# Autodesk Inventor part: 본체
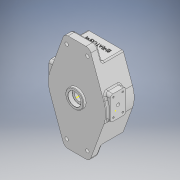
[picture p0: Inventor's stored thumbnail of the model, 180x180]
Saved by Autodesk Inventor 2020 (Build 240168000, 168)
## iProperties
Created: 2023-11
Part Number: 본체
Material: 일반
Document SubType Name: Modeling
Designer: CAD16
Density: 1 g/cm^3
Appearance: 기본값
Author: CAD16
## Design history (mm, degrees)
sketch "스케치1"
  geometry: L1 (-17.315, 94)-(17.315, 94); L2 (0, 94)-(0, 0); L3 (51.683, 18.811)-(26.711, 87.42); L4 (-51.683, 18.811)-(-26.711, 87.42); L5 (-55, 0)-(55, 0); L6 (51.683, -18.811)-(26.711, -87.42); L7 (-51.683, -18.811)-(-26.711, -87.42); L8 (-17.315, -94)-(17.315, -94); A1 r 55 centre (0, 0) between (-51.683, 18.811) and (51.683, 18.811); A2 r 10 centre (17.315, 84) between (26.711, 87.42) and (17.315, 94); A3 r 10 centre (-17.315, 84) between (-17.315, 94) and (-26.711, 87.42); A4 r 10 centre (-17.315, -84) between (-26.711, -87.42) and (-17.315, -94); A5 r 10 centre (17.315, -84) between (17.315, -94) and (26.711, -87.42); 7 further points
  constraints: 16 end point, 12 point on circle, 9 tangent, 8 point on line, 6 symmetric about line, 5 centre point, 2 equal radius, 2 horizontal, 2 midpoint, 1 coincident, 1 vertical
  dimensions: "d0" = 94 distance from line of point (0, 0) L1; "d1" = 110 diameter of A1; "d4" = 40 deg angle of L3 L4; "d119" = 10 radius of A2; "d120" = 10 radius of A3
extrude "돌출1" new body sketch "스케치1" distance "d5" = 15; taper "d6" = 0 deg
sketch "스케치2"
  geometry: L1 (-26.711, -87.42)-(-51.683, -18.811) reference; L2 (17.315, -94)-(-17.315, -94) reference; L3 (51.683, -18.811)-(26.711, -87.42) reference; L4 (26.711, 87.42)-(51.683, 18.811) reference; L5 (-17.315, 94)-(17.315, 94) reference; L6 (-51.683, 18.811)-(-26.711, 87.42) reference; L7 (-51.683, 18.811)-(-24.317, 94) reference; L8 (-33.78, 68)-(33.78, 68); L9 (24.317, 94)-(51.683, 18.811) reference; L10 (-24.317, -94)-(-51.683, -18.811) reference; L11 (-33.78, -68)-(33.78, -68); L12 (51.683, -18.811)-(24.317, -94) reference; L13 (24.317, 94)-(51.683, 18.811) reference; L14 (51.683, -18.811)-(24.317, -94) reference; L15 (-24.317, -94)-(-51.683, -18.811) reference; L16 (-51.683, 18.811)-(-24.317, 94) reference; L17 (-33.78, 68)-(-51.683, 18.811); L18 (-51.683, -18.811)-(-33.78, -68); L19 (33.78, -68)-(51.683, -18.811); L20 (51.683, 18.811)-(33.78, 68); C1 r 55 at (0, 0); A1 r 55 centre (0, 0) between (-51.683, 18.811) and (-51.683, -18.811) reference; A2 r 55 centre (0, 0) between (51.683, -18.811) and (51.683, 18.811) reference; A3 r 55 centre (0, 0) between (51.683, -18.811) and (51.683, 18.811) reference; A4 r 55 centre (0, 0) between (-51.683, 18.811) and (-51.683, -18.811) reference; A5 r 55 centre (0, 0) between (51.683, -18.811) and (51.683, 18.811) reference; A6 r 10 centre (17.315, 84) between (26.711, 87.42) and (17.315, 94) reference; A7 r 10 centre (-17.315, 84) between (-17.315, 94) and (-26.711, 87.42) reference; A8 r 10 centre (-17.315, -84) between (-26.711, -87.42) and (-17.315, -94) reference; A9 r 10 centre (17.315, -84) between (17.315, -94) and (26.711, -87.42) reference; 5 further points
  constraints: 12 end point, 4 point on line, 4 tangent, 3 collinear, 2 horizontal, 1 centre point, 1 coincident
  dimensions: "d7" = 68 distance from line of point (0, 0) L8; "d8" = 68 distance from line of point (0, 0) L11; "d9" = 110 diameter of C1
extrude "돌출2" join sketch "스케치2" distance "d10" = 40; taper "d11" = 0 deg
node "작업 평면1"
sketch "스케치13"
  geometry: L1 (0, 0)-(25, 0); L2 (25, 0)-(25, 61); L3 (25, 0)-(25, -61); C1 r 8 at (0, 0) reference; 1 further point
  constraints: 6 end point, 1 horizontal, 1 perpendicular, 1 vertical
  dimensions: "d34" = 25 distance of L1.start L1.end; "d35" = 61 distance of L1.end L2.end; "d36" = 61 distance of L1.end L3.end
hole "구멍1" sketch "스케치13" at (25, 61), (25, -61) diameter "d37" = 4.917; stored, may be unused: countersink angle "d41" = 90 deg, drill point angle "d43" = 120 deg; dims "d38" = 12, "d39" = 4, "d40" = 2, "d42" = 14
fillet "모깎기4" dims "d112" = 3
fillet "모깎기5" dims "d113" = 3
sketch "스케치21"
  geometry: L1 (0, 37)-(63.358, 37) reference; 3 further points
  constraints: 1 midpoint, 1 vertical alignment, 1 other
  dimensions: "d115" = 15 distance from line of L1 point (31.679, 22)
feature "엠보싱1" sketch "스케치21" dims "d116" = 0.5, "d117" = 0
sketch "스케치25"
  geometry: 1 further point
sketch "스케치26"
  geometry: L1 (0, 0)-(0, 9); C1 r 40 at (0, 9)
  constraints: 2 end point, 1 centre point, 1 coincident, 1 vertical
  dimensions: "d125" = 9 distance of L1.start L1.end; "d126" = 80 diameter of C1
extrude "돌출11" cut sketch "스케치26" distance "d127" = 30; taper "d128" = 0 deg
sketch "스케치27"
  geometry: C1 r 17.5 at (0, 0); 1 further point
  constraints: 1 centre point, 1 coincident
  dimensions: "d129" = 35 diameter of C1
extrude "돌출12" join sketch "스케치27" distance "d130" = 5; taper "d131" = 0 deg
chamfer "모따기2" distance "d132" = 1; stored, may be unused: second distance "d133" = 2, angle "d134" = 45 deg
sketch "스케치28"
  geometry: C1 r 12.5 at (0, 0); 1 further point
  constraints: 1 centre point, 1 coincident
  dimensions: "d135" = 25 diameter of C1
extrude "돌출13" cut sketch "스케치28" distance "d136" = 8.4; taper "d137" = 0 deg
sketch "스케치29"
  geometry: 1 further point
sketch "스케치30"
  geometry: C1 r 12.5 at (0, -9) reference; C2 r 10 at (0, -9); 1 further point
  constraints: 1 centre point, 1 coincident
  dimensions: "d138" = 20 diameter of C2
extrude "돌출14" cut sketch "스케치30" distance "d139" = 10; taper "d140" = 0 deg
sketch "스케치31"
  geometry: C1 r 8 at (0, 0); 1 further point
  constraints: 1 centre point, 1 coincident
  dimensions: "d141" = 16 diameter of C1
extrude "돌출15" cut sketch "스케치31" extent not by distance; stored distance "d142" = 10; taper "d143" = 0 deg
node "작업 평면2"
sketch "스케치34"
  geometry: L1 (63.459, -40)-(58.542, -40) reference; L2 (56.5, -40)-(52.4, -40); L3 (52.4, -40)-(52.4, -38.1); L4 (52.9, -37.6)-(56, -37.6); L5 (56.5, -38.1)-(56.5, -40); L6 (49, -40)-(-31, -40) reference; L7 (9, -40)-(9, -28.722); A1 r 0.5 centre (56, -38.1) between (56.5, -38.1) and (56, -37.6); A2 r 0.5 centre (52.9, -38.1) between (52.9, -37.6) and (52.4, -38.1); 3 further points
  constraints: 10 end point, 5 point on line, 4 point on circle, 4 tangent, 2 centre point, 2 parallel, 1 equal radius, 1 horizontal, 1 midpoint, 1 perpendicular, 1 vertical
  dimensions: "d145" = 4.1 distance of point (52.4, -37.6) point (56.5, -37.6); "d146" = 2.4 distance of point (56.5, -37.6) L2.start; "d147" = 0.5 radius of A1; "d148" = 47.5 distance from line of L2.start L7
revolve "회전3" sketch "스케치34" stored, may be unused: angle "d149" = 90 deg
sketch "스케치35"
  geometry: L1 (-26.702, 6)-(-22.517, 6); L2 (22.517, 6)-(26.702, 6); L3 (-26.702, -6)-(-25.515, -6); L4 (25.515, -6)-(26.702, -6); L5 (-28.373, -6)-(-26.108, -6); C1 r 40 at (0, 0) reference; C2 r 43.4 at (0, 0) reference; C3 r 10 at (0, -9) reference; C4 r 47.5 at (0, 0) reference; A1 r 29 centre (0, 0) between (28.68, -4.296) and (28.68, 4.296); A2 r 29 centre (0, 0) between (-28.68, 4.296) and (-28.68, -4.296); A3 r 24 centre (0, -9) between (-20.785, 3) and (-23.552, -4.385); A4 r 24 centre (0, -9) between (23.552, -4.385) and (20.785, 3); A5 r 2 centre (26.702, 4) between (28.68, 4.296) and (26.702, 6); A6 r 2 centre (26.702, -4) between (26.702, -6) and (28.68, -4.296); A7 r 2 centre (-26.702, 4) between (-26.702, 6) and (-28.68, 4.296); A8 r 2 centre (-22.517, 4) between (-20.785, 3) and (-22.517, 6); A9 r 2 centre (22.517, 4) between (22.517, 6) and (20.785, 3); A10 r 2 centre (-25.515, -4) between (-25.515, -6) and (-23.552, -4.385); A11 r 2 centre (-26.702, -4) between (-28.68, -4.296) and (-26.702, -6); A12 r 2 centre (25.515, -4) between (23.552, -4.385) and (25.515, -6); 9 further points
  constraints: 32 point on circle, 17 tangent, 12 centre point, 10 end point, 9 point on line, 3 equal radius, 3 horizontal, 2 coincident, 2 parallel, 1 midpoint, 1 vertical alignment
  dimensions: "d156" = 2 radius of A5; "d157" = 2 radius of A7 (derived); "d158" = 2 radius of A9 (derived); "d159" = 2 radius of A10 (derived); "d160" = 2 radius of A11 (derived); "d161" = 24 radius of A4; "d162" = 29 radius of A1; "d163" = 29 radius of A2; "d164" = 24 radius of A3; "d165" = 25.5147 horizontal distance of point (0, -9) A10.centre; "d166" = 26.70206 horizontal distance of point (0, -9) A7.centre
extrude "돌출16" cut sketch "스케치35" distance "d167" = 12; taper "d168" = 0 deg
node "작업 평면3"
sketch "스케치36"
  geometry: L1 (25.483, 10)-(-10.517, 10); L2 (-15.517, 5)-(-15.517, -15); L3 (-10.517, -20)-(25.483, -20); L4 (30.483, -15)-(30.483, 5); L5 (30.483, 10)-(-15.517, -20); L6 (-15.517, 10)-(30.483, -20); L7 (-16.5, 20)-(16.5, 20) reference; A1 r 5 centre (25.483, 5) between (30.483, 5) and (25.483, 10); A2 r 5 centre (25.483, -15) between (25.483, -20) and (30.483, -15); A3 r 5 centre (-10.517, -15) between (-15.517, -15) and (-10.517, -20); A4 r 5 centre (-10.517, 5) between (-10.517, 10) and (-15.517, 5); 2 further points
  constraints: 12 end point, 8 point on circle, 8 point on line, 8 tangent, 4 centre point, 3 equal radius, 2 midpoint, 2 parallel, 1 horizontal, 1 perpendicular
  dimensions: "d172" = 30 distance of L6.start L5.end; "d173" = 46 distance of L5.end L6.end; "d175" = 25 distance from line of L7 point (7.483, -5); "d176" = 9 distance of point (0, 0) point (7.483, -5); "d179" = 5 radius of A1 (derived)
extrude "돌출17" join sketch "스케치36" stored distance "d177" = 12; taper "d178" = 0 deg
sketch "스케치37"
  geometry: 1 further point
sketch "스케치38"
  geometry: 1 further point
sketch "스케치39"
  geometry: L1 (-10, 25.483)-(-10, -10.517) reference; L2 (-10, 7.483)-(5, 7.483); L3 (15, 30.483)-(-5, 30.483) reference; L4 (5, 30.483)-(5, 4.615); L5 (10, 4.615)-(-2, 4.615) reference; C1 r 3 at (5, 7.483); 1 further point
  constraints: 4 end point, 2 midpoint, 2 point on line, 1 centre point, 1 coincident, 1 horizontal, 1 vertical
  dimensions: "d180" = 6 diameter of C1
extrude "돌출18" cut sketch "스케치39" stored distance "d181" = 12; taper "d182" = 0 deg
sketch "스케치40"
  geometry: L1 (10, 49)-(10, -31) reference; L2 (10, 13.296)-(-2, 13.296) reference; L3 (5, 7.483)-(5, 24.483); L4 (5, 24.483)-(14, 24.483); L5 (40, 18.811)-(-15, 18.811) reference; L6 (5, 24.483)-(-4, 24.483); L7 (-10, 25.483)-(-10, -10.517) reference; C1 r 3 at (5, 7.483) reference; 1 further point
  constraints: 6 end point, 1 parallel, 1 perpendicular, 1 vertical
  dimensions: "d183" = 17 distance of L3.start L3.end; "d184" = 9 distance of L3.end L4.end; "d185" = 9 distance of L3.end L6.end
hole "구멍5" sketch "스케치40" at (14, 24.483), (-4, 24.483) diameter "d186" = 3.242; stored, may be unused: countersink angle "d190" = 90 deg, drill point angle "d192" = 120 deg; dims "d187" = 8, "d188" = 4, "d189" = 2, "d191" = 10
sketch "스케치41"
  geometry: L1 (5, 7.483)-(20, 7.483); L2 (20, -10.517)-(20, 25.483) reference; L3 (5, 7.483)-(5, -9.517); L4 (5, -9.517)-(14, -9.517); L5 (5, -9.517)-(-4, -9.517); C1 r 3 at (5, 7.483) reference; 1 further point
  constraints: 8 end point, 1 horizontal, 1 midpoint, 1 perpendicular, 1 vertical
  dimensions: "d193" = 9 distance of L3.end L5.end; "d194" = 9 distance of L3.end L4.end; "d195" = 17 distance of L1.start L3.end
hole "구멍6" sketch "스케치41" at (-4, -9.517), (14, -9.517) diameter "d196" = 3.242; stored, may be unused: countersink angle "d200" = 90 deg, drill point angle "d202" = 120 deg; dims "d197" = 8, "d198" = 4, "d199" = 2, "d201" = 10
fillet "모깎기9" dims "d203" = 3
sketch "스케치42"
  geometry: L1 (0, -9)-(0, 17); L2 (0, 17)-(15, 17); L3 (0, 17)-(-15, 17)
  constraints: 6 end point, 1 horizontal, 1 perpendicular, 1 vertical
  dimensions: "d204" = 26 distance of L1.start L1.end; "d205" = 15 distance of L1.end L2.end; "d206" = 15 distance of L1.end L3.end
fillet "모깎기10" dims "d207" = 2
sketch "스케치43"
  geometry: L1 (0, 0)-(0, 79); L2 (0, 79)-(20, 79); L3 (0, 79)-(-20, 79); C1 r 12.5 at (0, 0) reference; 1 further point
  constraints: 6 end point, 2 horizontal, 1 vertical
  dimensions: "d208" = 79 distance of L1.start L1.end; "d209" = 20 distance of L1.end L2.end; "d210" = 20 distance of L1.end L3.end
hole "구멍7" sketch "스케치43" at (-20, 79), (20, 79) diameter "d211" = 6.6; stored, may be unused: countersink angle "d215" = 90 deg, drill point angle "d217" = 120 deg; dims "d212" = 8, "d213" = 11, "d214" = 6.6, "d216" = 10
sketch "스케치44"
  geometry: L1 (12.731, 20)-(12.5, 19.6); L2 (12.5, 20)-(12.5, 11.6) reference; L3 (-16.5, 20)-(16.5, 20) reference; L4 (12.5, 20)-(12.5, 19.6); L5 (12.5, 20)-(12.731, 20); L6 (0, 20)-(0, 13.232); 1 further point
  constraints: 8 end point, 2 perpendicular, 2 point on line, 1 midpoint, 1 vertical
  dimensions: "d218" = 0.4 distance of L1.end L2.start; "d219" = 30 deg angle of L2 L1
revolve "회전4" sketch "스케치44" stored, may be unused: angle "d220" = 90 deg
fillet "모깎기11" dims "d221" = 0.2
sketch "스케치45"
  geometry: 1 further point
hole "구멍8" sketch "스케치42" diameter "d222" = 3.242; stored, may be unused: countersink angle "d226" = 90 deg, drill point angle "d228" = 120 deg; dims "d223" = 8, "d224" = 4, "d225" = 2, "d227" = 10
node "솔리드1"
mirror "미러2"
mirror "미러6"
mirror "미러7"
node "투영된 루프1"
feature "A9D066F2-1C7D-4E18-AEED-F7BC21143FA4" dims "d211" = 6.6, "d212" = 8, "d213" = 11, "d214" = 6.6, "d215" = 90 deg, "d216" = 10, "d217" = 120 deg
other parameters: "d27" = 59, "d65" = 58, "d66" = 48, "d68" = 12, "d144" = 59, "d150" = 58, "d153" = 3, "d154" = 12, "d155" = 48, "d169" = 59
